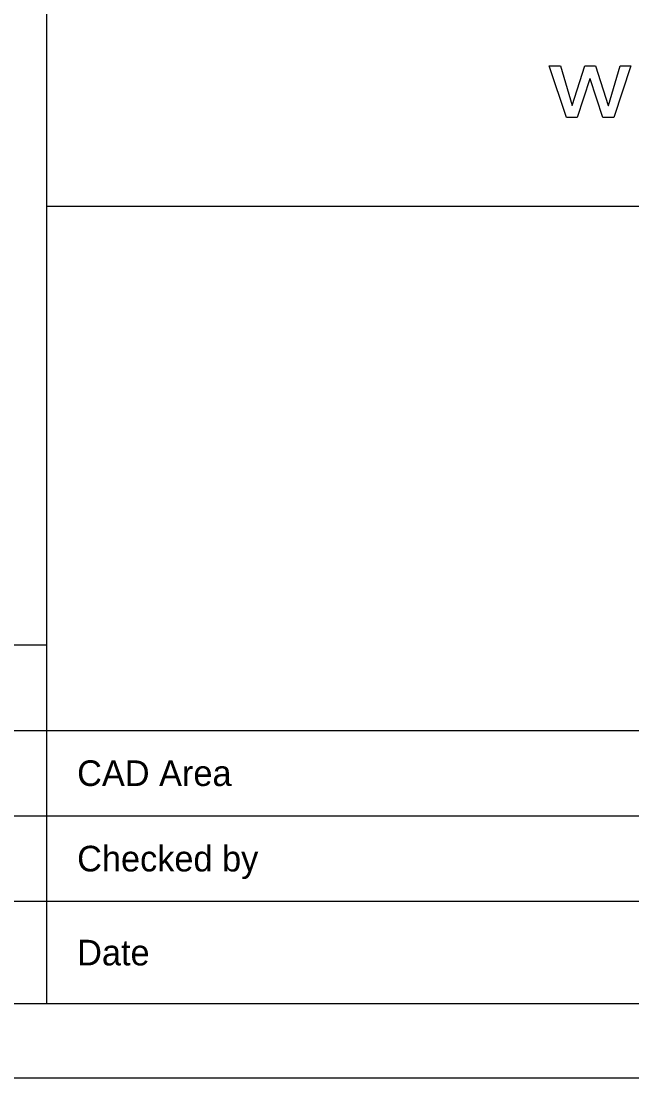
# Model space of a CAD drawing. Extents: x 613360 to 613780, y 4825621 to 4825911.
# Drawn here: x 613709.87 to 613731.3, y 4825620.91 to 4825658.01 of the extents above; entities that cross this region are included whole.
import ezdxf

# ---------------------------------------------------------------- set-up
doc = ezdxf.new("R2010")
doc.units = 0
for name, color, linetype in [('G-ANNO-TTLB-TEXT', 7, 'Continuous'), ('G-TTLB-LOGO', 7, 'Continuous'), ('G-TTLB-OTLN', 7, 'Continuous'), ('G-TTLB-OTLN-PB', 7, 'Continuous')]:
    doc.layers.add(name, color=color, linetype=linetype)

msp = doc.modelspace()

# ---------------------------------------------------------------- linework, layer by layer
at = {"layer": 'G-TTLB-LOGO'}
for p, q in [((613729.006, 4825654.626), (613728.4, 4825656.446)), ((613728.4, 4825656.446), (613728.791, 4825656.446)), ((613728.791, 4825656.446), (613729.202, 4825655.056)), ((613729.21, 4825655.056), (613729.644, 4825656.446)), ((613729.644, 4825656.446), (613730.024, 4825656.446)), ((613730.024, 4825656.446), (613730.466, 4825655.056)), ((613730.474, 4825655.056), (613730.885, 4825656.446)), ((613731.265, 4825656.446), (613730.662, 4825654.626)), ((613730.885, 4825656.446), (613731.265, 4825656.446)), ((613729.828, 4825655.993), (613729.383, 4825654.626)), ((613729.836, 4825655.993), (613729.828, 4825655.993)), ((613730.286, 4825654.626), (613729.836, 4825655.993)), ((613729.202, 4825655.056), (613729.21, 4825655.056)), ((613730.466, 4825655.056), (613730.474, 4825655.056)), ((613729.383, 4825654.626), (613729.006, 4825654.626)), ((613730.662, 4825654.626), (613730.286, 4825654.626))]:
    msp.add_line(p, q, dxfattribs=at)
msp.add_lwpolyline([(613728.791, 4825656.446), (613729.202, 4825655.056), (613729.21, 4825655.056), (613729.644, 4825656.446), (613730.024, 4825656.446), (613730.466, 4825655.056), (613730.474, 4825655.056), (613730.885, 4825656.446), (613731.265, 4825656.446), (613730.662, 4825654.626), (613730.286, 4825654.626), (613729.836, 4825655.993), (613729.828, 4825655.993), (613729.383, 4825654.626), (613729.006, 4825654.626), (613728.4, 4825656.446), (613728.791, 4825656.446)], dxfattribs=at)
at = {"layer": 'G-TTLB-OTLN'}
for p, q in [((613710.777, 4825623.508), (613710.777, 4825815.929)), ((613774.178, 4825651.507), (613710.777, 4825651.507)), ((613380.085, 4825636.108), (613710.777, 4825636.108)), ((613380.086, 4825633.107), (613774.178, 4825633.107)), ((613380.086, 4825630.107), (613749.425, 4825630.107)), ((613380.086, 4825627.107), (613749.425, 4825627.107))]:
    msp.add_line(p, q, dxfattribs=at)
msp.add_lwpolyline([(613380.085, 4825892.077), (613774.178, 4825892.077), (613774.178, 4825623.508), (613380.085, 4825623.508)], close=True, dxfattribs=at)
at = {"layer": 'G-TTLB-OTLN-PB'}
msp.add_lwpolyline([(613359.578, 4825620.908), (613780.27, 4825620.908), (613780.27, 4825894.677), (613359.578, 4825894.677)], close=True, dxfattribs=at)

# ---------------------------------------------------------------- texts
at = {"layer": 'G-ANNO-TTLB-TEXT'}
for s, p in [('CAD Area', (613711.837, 4825631.157)), ('Checked by', (613711.837, 4825628.157)), ('Date', (613711.837, 4825624.857))]:
    msp.add_text(s, height=0.9, dxfattribs=at).set_placement(p)

doc.saveas('drawing.dxf')
